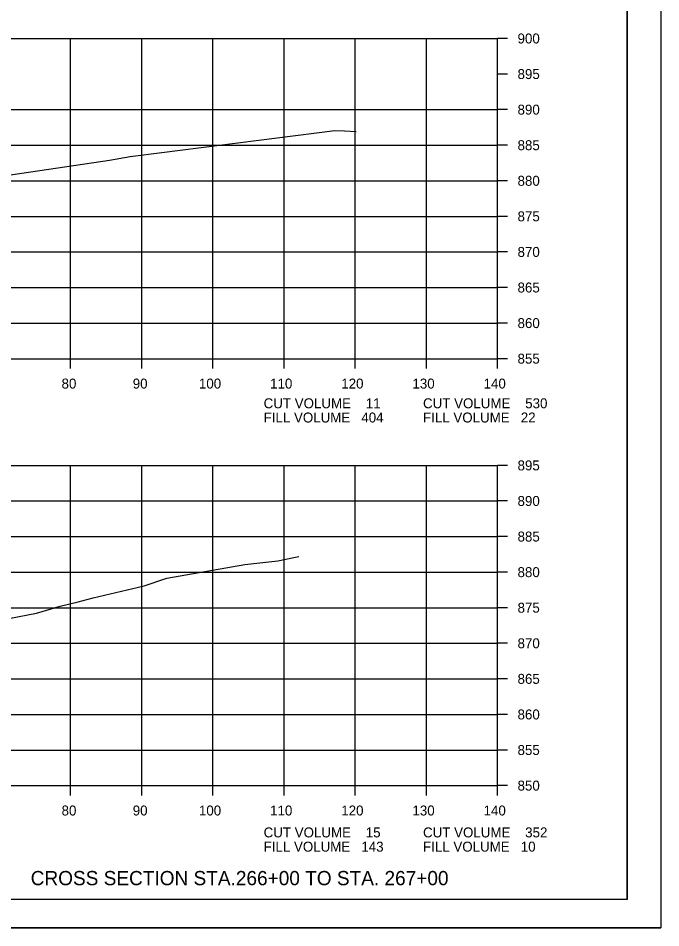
# Model space of a CAD drawing. Extents: x 1486524 to 1499135, y 326561 to 337924.
# Drawn here: x 1489055.5 to 1489145.8, y 329792.6 to 329920.4 of the extents above; entities that cross this region are included whole.
import ezdxf

# ---------------------------------------------------------------- set-up
doc = ezdxf.new("R2010")
doc.units = 0
for name, color, linetype in [('E_Const Align', 7, 'Continuous'), ('E_Const Align Station', 7, 'Continuous'), ('E_Ownership Information', 7, 'Continuous'), ('E_Property Line', 7, 'Continuous'), ('E_Proposed ROW Fig Annot', 7, 'Continuous'), ('E_Quarter Calls', 7, 'Continuous'), ('E_Tract Number', 7, 'Continuous')]:
    doc.layers.add(name, color=color, linetype=linetype)

msp = doc.modelspace()

# ---------------------------------------------------------------- linework, layer by layer
at = {"layer": 'E_Const Align'}
for p, q in [((1489122.89, 329872.56), (1489122.89, 329917.56)), ((1489124.29, 329917.56), (1489122.89, 329917.56)), ((1489124.29, 329912.56), (1489122.89, 329912.56)), ((1489124.29, 329907.56), (1489122.89, 329907.56)), ((1489124.29, 329902.56), (1489122.89, 329902.56)), ((1489124.29, 329897.56), (1489122.89, 329897.56)), ((1489124.29, 329892.56), (1489122.89, 329892.56)), ((1489124.29, 329887.56), (1489122.89, 329887.56)), ((1489124.29, 329882.56), (1489122.89, 329882.56)), ((1489124.29, 329877.56), (1489122.89, 329877.56)), ((1488842.89, 329872.56), (1489122.89, 329872.56)), ((1489062.89, 329871.16), (1489062.89, 329872.56)), ((1489072.89, 329871.16), (1489072.89, 329872.56)), ((1489082.89, 329871.16), (1489082.89, 329872.56)), ((1489092.89, 329871.16), (1489092.89, 329872.56)), ((1489102.89, 329871.16), (1489102.89, 329872.56)), ((1489112.89, 329871.16), (1489112.89, 329872.56)), ((1489122.89, 329871.16), (1489122.89, 329872.56)), ((1489124.29, 329872.56), (1489122.89, 329872.56)), ((1489122.89, 329812.56), (1489122.89, 329857.56)), ((1489124.29, 329857.56), (1489122.89, 329857.56)), ((1489124.29, 329852.56), (1489122.89, 329852.56)), ((1489124.29, 329847.56), (1489122.89, 329847.56)), ((1489124.29, 329842.56), (1489122.89, 329842.56)), ((1489124.29, 329837.56), (1489122.89, 329837.56)), ((1489124.29, 329832.56), (1489122.89, 329832.56)), ((1489124.29, 329827.56), (1489122.89, 329827.56)), ((1489124.29, 329822.56), (1489122.89, 329822.56)), ((1489124.29, 329817.56), (1489122.89, 329817.56)), ((1488842.89, 329812.56), (1489122.89, 329812.56)), ((1489062.89, 329811.16), (1489062.89, 329812.56)), ((1489072.89, 329811.16), (1489072.89, 329812.56)), ((1489082.89, 329811.16), (1489082.89, 329812.56)), ((1489092.89, 329811.16), (1489092.89, 329812.56)), ((1489102.89, 329811.16), (1489102.89, 329812.56)), ((1489112.89, 329811.16), (1489112.89, 329812.56)), ((1489122.89, 329811.16), (1489122.89, 329812.56)), ((1489124.29, 329812.56), (1489122.89, 329812.56))]:
    msp.add_line(p, q, dxfattribs=at)
at = {"layer": 'E_Ownership Information'}
for p, q in [((1488842.89, 329917.56), (1489122.89, 329917.56)), ((1489062.89, 329872.56), (1489062.89, 329917.56)), ((1489072.89, 329872.56), (1489072.89, 329917.56)), ((1489082.89, 329872.56), (1489082.89, 329917.56)), ((1489092.89, 329872.56), (1489092.89, 329917.56)), ((1489102.89, 329872.56), (1489102.89, 329917.56)), ((1489112.89, 329872.56), (1489112.89, 329917.56)), ((1489122.89, 329872.56), (1489122.89, 329917.56)), ((1488842.89, 329907.56), (1489122.89, 329907.56)), ((1488842.89, 329902.56), (1489122.89, 329902.56)), ((1488842.89, 329897.56), (1489122.89, 329897.56)), ((1488842.89, 329892.56), (1489122.89, 329892.56)), ((1488842.89, 329887.56), (1489122.89, 329887.56)), ((1488842.89, 329882.56), (1489122.89, 329882.56)), ((1488842.89, 329877.56), (1489122.89, 329877.56)), ((1488842.89, 329872.56), (1489122.89, 329872.56)), ((1488842.89, 329857.56), (1489122.89, 329857.56)), ((1489062.89, 329812.56), (1489062.89, 329857.56)), ((1489072.89, 329812.56), (1489072.89, 329857.56)), ((1489082.89, 329812.56), (1489082.89, 329857.56)), ((1489092.89, 329812.56), (1489092.89, 329857.56)), ((1489102.89, 329812.56), (1489102.89, 329857.56)), ((1489112.89, 329812.56), (1489112.89, 329857.56)), ((1489122.89, 329812.56), (1489122.89, 329857.56)), ((1488842.89, 329852.56), (1489122.89, 329852.56)), ((1488842.89, 329847.56), (1489122.89, 329847.56)), ((1488842.89, 329842.56), (1489122.89, 329842.56)), ((1488842.89, 329837.56), (1489122.89, 329837.56)), ((1488842.89, 329832.56), (1489122.89, 329832.56)), ((1488842.89, 329827.56), (1489122.89, 329827.56)), ((1488842.89, 329822.56), (1489122.89, 329822.56)), ((1488842.89, 329817.56), (1489122.89, 329817.56)), ((1488842.89, 329812.56), (1489122.89, 329812.56))]:
    msp.add_line(p, q, dxfattribs=at)
at = {"layer": 'E_Property Line'}
for q in [(1489141.07, 330002.02), (1488824.89, 329796.56)]:
    msp.add_line((1489141.07, 329796.56), q, dxfattribs=at)
at = {"layer": 'E_Quarter Calls'}
msp.add_line((1488812.48, 329792.58), (1489145.82, 329792.58), dxfattribs=at)
for points in [[(1488812.48, 330005.91), (1489145.82, 330005.91), (1489145.82, 329792.57), (1488812.48, 329792.57)], [(1489058.81, 330002.02), (1489058.81, 329992.14), (1489094.54, 329992.14), (1489094.54, 329989.22), (1489117.74, 329989.22), (1489117.74, 329964.88), (1489141.07, 329964.88), (1489141.07, 329796.56), (1488824.89, 329796.56), (1488824.89, 330002.02)]]:
    msp.add_lwpolyline(points, close=True, dxfattribs=at)
at = {"layer": 'E_Tract Number'}
for points in [[(1489052.21, 329898.08), (1489068.36, 329900.45), (1489071.25, 329900.99), (1489075.73, 329901.54), (1489100.02, 329904.64), (1489101.36, 329904.57), (1489103.02, 329904.49)], [(1489054.23, 329836.05), (1489058.11, 329836.78), (1489061.41, 329837.8), (1489063.97, 329838.38), (1489066.06, 329838.96), (1489073.22, 329840.64), (1489076.4, 329841.69), (1489087.38, 329843.64), (1489092.02, 329844.13), (1489094.26, 329844.62), (1489094.96, 329844.77)]]:
    msp.add_lwpolyline(points, dxfattribs=at)

# ---------------------------------------------------------------- texts
at = {"layer": 'E_Const Align Station'}
for s, p in [('900', (1489125.69, 329916.86)), ('895', (1489125.69, 329911.86)), ('890', (1489125.69, 329906.86)), ('885', (1489125.69, 329901.86)), ('880', (1489125.69, 329896.86)), ('875', (1489125.69, 329891.86)), ('870', (1489125.69, 329886.86)), ('865', (1489125.69, 329881.86)), ('860', (1489125.69, 329876.86)), ('855', (1489125.69, 329871.86)), ('80', (1489061.62, 329868.36)), ('90', (1489071.62, 329868.36)), ('100', (1489080.92, 329868.36)), ('110', (1489090.92, 329868.36)), ('120', (1489100.92, 329868.36)), ('130', (1489110.92, 329868.36)), ('140', (1489120.92, 329868.36)), ('CUT VOLUME    11', (1489090.01, 329865.59)), ('CUT VOLUME    530', (1489112.41, 329865.59)), ('FILL VOLUME   404', (1489090.01, 329863.59)), ('FILL VOLUME   22', (1489112.41, 329863.59)), ('895', (1489125.69, 329856.86)), ('890', (1489125.69, 329851.86)), ('885', (1489125.69, 329846.86)), ('880', (1489125.69, 329841.86)), ('875', (1489125.69, 329836.86)), ('870', (1489125.69, 329831.86)), ('865', (1489125.69, 329826.86)), ('860', (1489125.69, 329821.86)), ('855', (1489125.69, 329816.86)), ('850', (1489125.69, 329811.86)), ('80', (1489061.62, 329808.36)), ('90', (1489071.62, 329808.36)), ('100', (1489080.92, 329808.36)), ('110', (1489090.92, 329808.36)), ('120', (1489100.92, 329808.36)), ('130', (1489110.92, 329808.36)), ('140', (1489120.92, 329808.36)), ('CUT VOLUME    15', (1489090.01, 329805.28)), ('CUT VOLUME    352', (1489112.41, 329805.28)), ('FILL VOLUME   143', (1489090.01, 329803.28)), ('FILL VOLUME   10', (1489112.41, 329803.28))]:
    msp.add_text(s, height=1.4, dxfattribs=at).set_placement(p)
at = {"layer": 'E_Proposed ROW Fig Annot'}
msp.add_text('CROSS SECTION STA.266+00 TO STA. 267+00', height=2, dxfattribs=at).set_placement((1489057.28, 329798.56))

doc.saveas('drawing.dxf')
